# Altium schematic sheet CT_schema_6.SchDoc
size 143 x 123 mm
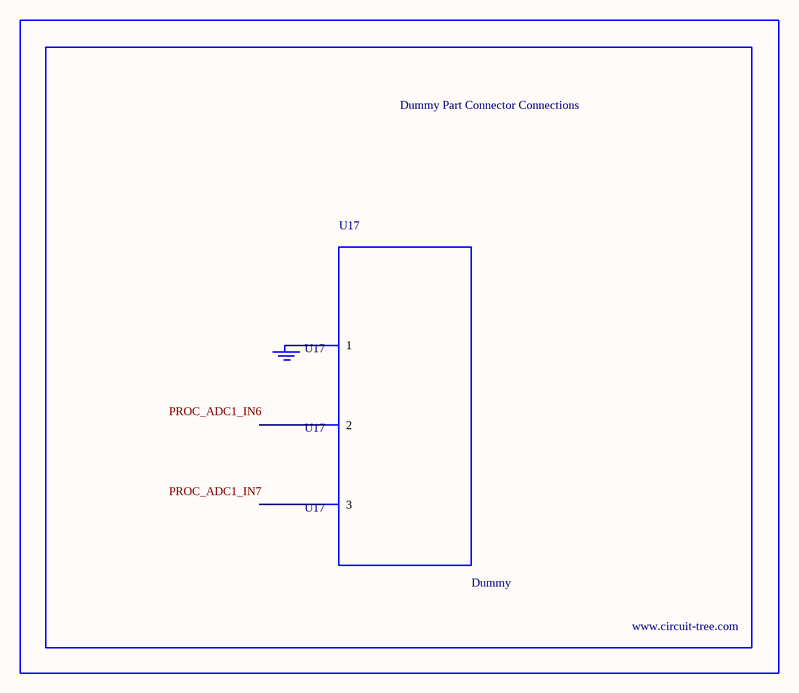
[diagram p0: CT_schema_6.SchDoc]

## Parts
BORDER5  (no value)
GND_INSTANCE_5_0  (no value)
U17  Dummy  [DUMMY_PACKAGE_152]

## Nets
NetGND_INSTANCE_5_0_0: GND_INSTANCE_5_0.0(GND) U17.1

Not connected (* = marked no-connect by the designer): U17 2 3

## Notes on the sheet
- Labels drawn without touching a wire or pin: PROC_ADC1_IN6, PROC_ADC1_IN7

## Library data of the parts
BORDER5 = BORDER_PAGE5
GND_INSTANCE_5_0 = GND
